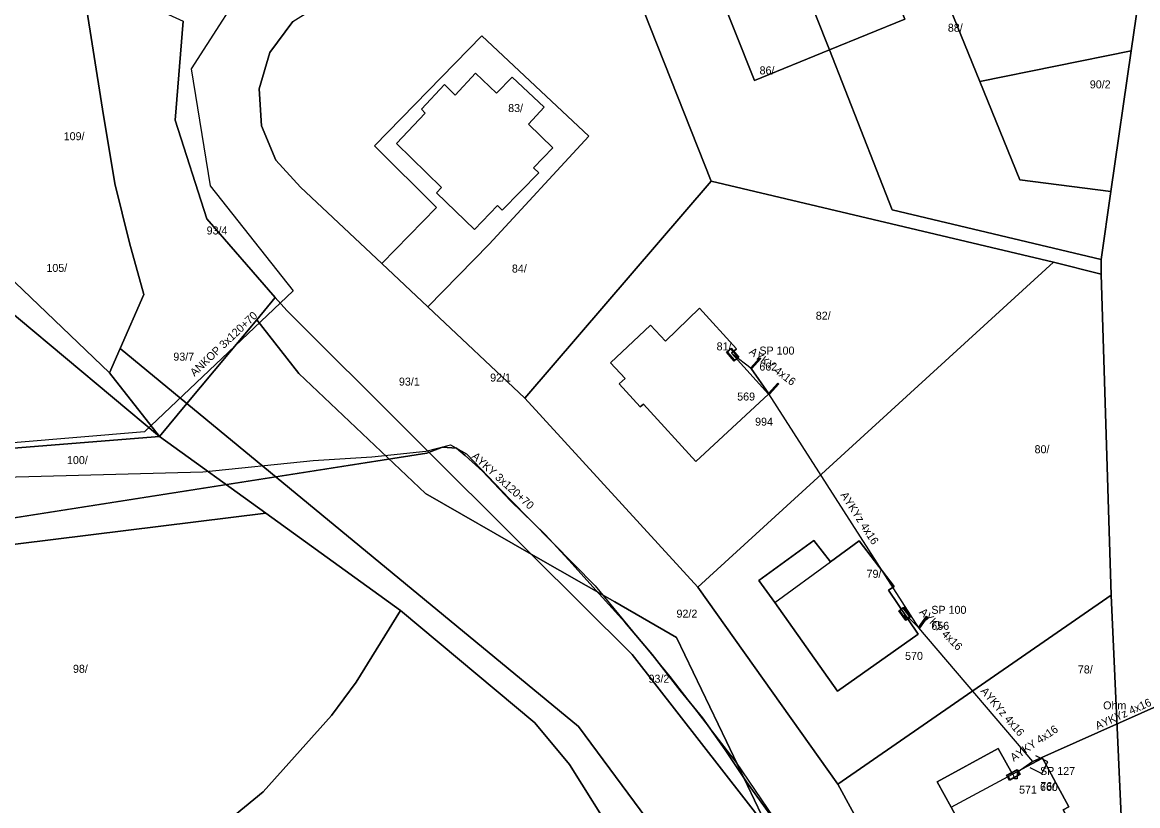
# Model space of a CAD drawing. Extents: x -793400 to -756198, y -1074141 to -1042963.
# Drawn here: x -783438.8 to -783334.3, y -1065213.5 to -1065140.1 of the extents above; entities that cross this region are included whole.
import ezdxf

# ---------------------------------------------------------------- set-up
doc = ezdxf.new("R2010")
doc.units = 0
for name, color, linetype in [('Parcela', 7, 'Continuous'), ('PB nn', 7, 'Continuous'), ('Popiskový text - Parcela', 7, 'Continuous'), ('Popiskový text - PB nn - sk_2 - SJZ', 7, 'Continuous'), ('Popiskový text - Přípojková skříň nn - SJZ', 7, 'Continuous'), ('Popiskový text - Přípojková skříň nn - Typ', 7, 'Continuous'), ('Popiskový text - Uzemnění - Odpor', 7, 'Continuous'), ('Popiskový text - Vedení nn kabelové', 7, 'Continuous'), ('Popiskový text - Vedení nn svod', 7, 'Continuous'), ('Popiskový text - Vedení nn venkovní izol', 7, 'Continuous'), ('Skříň', 7, 'Continuous'), ('Spojnice nn', 7, 'Continuous'), ('Spojnice vn', 7, 'Continuous'), ('Stavební objekt', 7, 'Continuous'), ('Vedení 22 kV kabelové', 7, 'Continuous'), ('Vedení nn kabelové', 7, 'Continuous'), ('Vedení nn svod', 7, 'Continuous'), ('Vedení nn venkovní izolované', 7, 'Continuous')]:
    doc.layers.add(name, color=color, linetype=linetype)

msp = doc.modelspace()

# ---------------------------------------------------------------- linework, layer by layer
at = {"layer": 'Parcela'}
for points in [[(-783334.89, -1065142.75), (-783349.08, -1065145.61), (-783359.09, -1065121.02), (-783336.58, -1065111.89), (-783333.19, -1065112.61), (-783331.29, -1065114.46), (-783330.21, -1065117.78), (-783332.76, -1065128.1)], [(-783333.46, -1065173.04), (-783333.27, -1065184.1), (-783332.18, -1065183.83), (-783332.44, -1065204.1), (-783331.2, -1065229.69), (-783329.02, -1065234.74), (-783333.33, -1065281.22), (-783340.36, -1065267.55), (-783335.58, -1065250.68), (-783334.84, -1065248.08), (-783334.44, -1065245.21), (-783335.73, -1065216.58), (-783336.76, -1065193.79), (-783337.72, -1065163.69), (-783337.71, -1065162.3), (-783336.8, -1065155.92), (-783334.89, -1065142.75), (-783332.76, -1065128.1), (-783330.21, -1065117.78), (-783325.71, -1065116.67), (-783328.95, -1065129.54), (-783331.93, -1065148.39), (-783333.28, -1065158.38), (-783333.36, -1065165.67)], [(-783359.09, -1065121.02), (-783349.08, -1065145.61), (-783345.34, -1065154.82), (-783336.8, -1065155.92), (-783337.71, -1065162.3), (-783357.29, -1065157.65), (-783363.17, -1065142.65), (-783356.12, -1065139.77), (-783359.98, -1065130.16), (-783367.03, -1065132.96), (-783370.11, -1065125.47)], [(-783374.09, -1065135.77), (-783370.22, -1065145.53), (-783363.17, -1065142.65), (-783357.29, -1065157.65), (-783337.71, -1065162.3), (-783337.72, -1065163.69), (-783342.17, -1065162.55), (-783374.26, -1065154.97), (-783383.74, -1065131.01), (-783370.11, -1065125.47), (-783367.03, -1065132.96)], [(-783356.12, -1065139.77), (-783363.17, -1065142.65), (-783367.03, -1065132.96), (-783359.98, -1065130.16)], [(-783383.74, -1065131.01), (-783374.26, -1065154.97), (-783391.75, -1065175.3), (-783400.84, -1065166.73), (-783395.07, -1065160.86), (-783385.75, -1065150.75), (-783395.76, -1065141.32), (-783405.84, -1065151.66), (-783400.01, -1065157.44), (-783405.15, -1065162.67), (-783412.76, -1065155.51), (-783415.07, -1065153), (-783416.41, -1065149.77), (-783416.64, -1065146.29), (-783415.63, -1065142.9), (-783413.48, -1065139.98), (-783410.44, -1065138.09)], [(-783363.17, -1065142.65), (-783370.22, -1065145.53), (-783374.09, -1065135.77), (-783367.03, -1065132.96)], [(-783416.87, -1065167.97), (-783423.43, -1065175.81), (-783429.68, -1065170.65), (-783427.46, -1065165.58), (-783428.81, -1065160.75), (-783430.17, -1065155.19), (-783431.34, -1065148.2), (-783433, -1065137.71), (-783432.01, -1065136.13), (-783425.83, -1065139.01), (-783423.77, -1065139.97), (-783424.51, -1065149.24), (-783421.56, -1065158.5), (-783415.13, -1065165.88)], [(-783433, -1065137.71), (-783431.34, -1065148.2), (-783430.17, -1065155.19), (-783428.81, -1065160.75), (-783427.46, -1065165.58), (-783429.68, -1065170.65), (-783430.68, -1065172.94), (-783446.93, -1065157.4), (-783446.89, -1065157.28), (-783447.25, -1065153.59), (-783445.62, -1065150.92), (-783447.67, -1065149.41), (-783450, -1065147.55), (-783450.24, -1065147.87), (-783451.27, -1065147.1), (-783449.11, -1065143.27), (-783443.11, -1065146.26), (-783440.09, -1065139.19)], [(-783395.07, -1065160.86), (-783400.84, -1065166.73), (-783405.15, -1065162.67), (-783400.01, -1065157.44), (-783405.84, -1065151.66), (-783395.76, -1065141.32), (-783385.75, -1065150.75)], [(-783334.89, -1065142.75), (-783336.8, -1065155.92), (-783345.34, -1065154.82), (-783349.08, -1065145.61)], [(-783342.17, -1065162.55), (-783375.51, -1065193.02), (-783391.75, -1065175.3), (-783374.26, -1065154.97)], [(-783430.68, -1065172.94), (-783426, -1065178.89), (-783448.04, -1065160.47), (-783447.05, -1065157.72), (-783446.93, -1065157.4)], [(-783452.51, -1065181.01), (-783462.8, -1065182.31), (-783462.64, -1065176.13), (-783453.07, -1065175.27), (-783453.17, -1065164.1), (-783453.76, -1065160.93), (-783453.28, -1065158.57), (-783448.04, -1065160.47), (-783426, -1065178.89), (-783449.86, -1065180.82), (-783451.98, -1065180.95)], [(-783336.76, -1065193.79), (-783362.38, -1065211.5), (-783375.51, -1065193.02), (-783342.17, -1065162.55), (-783337.72, -1065163.69)], [(-783414.06, -1065167.1), (-783391.13, -1065189.93), (-783401.04, -1065184.24), (-783412.92, -1065172.99), (-783416.87, -1065167.97), (-783415.13, -1065165.88)], [(-783375.37, -1065166.88), (-783371.9, -1065170.69), (-783372.35, -1065171.09), (-783368.88, -1065174.92), (-783375.71, -1065181.24), (-783380.62, -1065175.86), (-783380.92, -1065176.13), (-783382.9, -1065173.97), (-783382.34, -1065173.46), (-783383.7, -1065171.99), (-783379.95, -1065168.47), (-783378.54, -1065169.96)], [(-783375.37, -1065166.88), (-783378.54, -1065169.96), (-783379.95, -1065168.47), (-783383.7, -1065171.99), (-783382.34, -1065173.46), (-783382.9, -1065173.97), (-783380.92, -1065176.13), (-783380.62, -1065175.86), (-783375.71, -1065181.24), (-783368.88, -1065174.92), (-783372.35, -1065171.09), (-783371.9, -1065170.69)], [(-783346.09, -1065256.41), (-783341.85, -1065272.8), (-783351.87, -1065253.68), (-783380.31, -1065214.76), (-783386.7, -1065206.1), (-783423.43, -1065175.81), (-783416.87, -1065167.97), (-783412.92, -1065172.99), (-783401.04, -1065184.24), (-783391.13, -1065189.93), (-783381.67, -1065199.34), (-783368.9, -1065215.74)], [(-783423.43, -1065175.81), (-783426, -1065178.89), (-783430.68, -1065172.94), (-783429.68, -1065170.65)], [(-783341.85, -1065272.8), (-783345.64, -1065275.81), (-783354.48, -1065257.7), (-783360.91, -1065248.3), (-783363.87, -1065245.46), (-783374.02, -1065231.27), (-783383.09, -1065216.77), (-783387.54, -1065209.66), (-783390.81, -1065205.75), (-783403.39, -1065195.23), (-783416.03, -1065186.09), (-783426, -1065178.89), (-783423.43, -1065175.81), (-783386.7, -1065206.1), (-783380.31, -1065214.76), (-783351.87, -1065253.68)], [(-783449.1, -1065190.18), (-783453.6, -1065190.73), (-783451.98, -1065180.95), (-783449.86, -1065180.82), (-783426, -1065178.89), (-783416.03, -1065186.09)], [(-783416.03, -1065186.09), (-783403.39, -1065195.23), (-783407.54, -1065201.94), (-783409.86, -1065205.07), (-783416.28, -1065212.21), (-783421, -1065216.11), (-783424.16, -1065218.04), (-783438.03, -1065224.17), (-783441.5, -1065225.71), (-783447.41, -1065228.37), (-783452.73, -1065215.33), (-783452.34, -1065209.47), (-783459.78, -1065208.85), (-783460.26, -1065214.69), (-783460.3, -1065215.24), (-783468.73, -1065213.48), (-783469.27, -1065213.37), (-783464.68, -1065192.93), (-783464.13, -1065193.03), (-783454.3, -1065194.92), (-783453.6, -1065190.73), (-783449.1, -1065190.18)], [(-783364.63, -1065188.64), (-783363.08, -1065190.67), (-783360.38, -1065188.7), (-783357.12, -1065192.97), (-783357.65, -1065193.32), (-783354.87, -1065197.43), (-783362.42, -1065202.79), (-783368.31, -1065194.48), (-783369.79, -1065192.4)], [(-783364.63, -1065188.64), (-783369.79, -1065192.4), (-783368.31, -1065194.48), (-783362.42, -1065202.79), (-783354.87, -1065197.43), (-783357.65, -1065193.32), (-783357.12, -1065192.97), (-783360.38, -1065188.7), (-783363.08, -1065190.67)], [(-783372.84, -1065207.51), (-783368.9, -1065215.74), (-783381.67, -1065199.34), (-783391.13, -1065189.93), (-783383.31, -1065194.42), (-783377.51, -1065197.74)], [(-783336.76, -1065193.79), (-783335.73, -1065216.58), (-783338.92, -1065218.3), (-783341.26, -1065213.91), (-783340.73, -1065213.63), (-783343.2, -1065209.05), (-783346.03, -1065210.57), (-783347.35, -1065208.17), (-783353.07, -1065211.27), (-783351.78, -1065213.65), (-783346.93, -1065222.62), (-783354.11, -1065226.72), (-783362.38, -1065211.5)], [(-783383.09, -1065216.77), (-783436.26, -1065245.82), (-783436.65, -1065245.81), (-783436.74, -1065242.46), (-783438.03, -1065224.17), (-783424.16, -1065218.04), (-783421, -1065216.11), (-783416.28, -1065212.21), (-783409.86, -1065205.07), (-783407.54, -1065201.94), (-783403.39, -1065195.23), (-783390.81, -1065205.75), (-783387.54, -1065209.66)], [(-783347.35, -1065208.17), (-783346.03, -1065210.57), (-783343.2, -1065209.05), (-783340.73, -1065213.63), (-783341.26, -1065213.91), (-783338.92, -1065218.3), (-783346.93, -1065222.62), (-783351.78, -1065213.65), (-783353.07, -1065211.27)]]:
    msp.add_lwpolyline(points, close=True, dxfattribs=at)
for points in [[(-783346.09, -1065256.41), (-783368.9, -1065215.74), (-783372.84, -1065207.51), (-783377.51, -1065197.74), (-783383.31, -1065194.42), (-783391.13, -1065189.93), (-783414.06, -1065167.1), (-783415.13, -1065165.88), (-783421.56, -1065158.5), (-783424.51, -1065149.24), (-783423.77, -1065139.97)], [(-783413.48, -1065139.98), (-783415.63, -1065142.9), (-783416.64, -1065146.29), (-783416.41, -1065149.77), (-783415.07, -1065153), (-783412.76, -1065155.51), (-783405.15, -1065162.67), (-783400.84, -1065166.73), (-783391.75, -1065175.3), (-783375.51, -1065193.02), (-783362.38, -1065211.5), (-783354.11, -1065226.72), (-783342.64, -1065247.88), (-783340.83, -1065249.95), (-783338.15, -1065250.41), (-783336.55, -1065250), (-783334.84, -1065248.08), (-783335.58, -1065250.68), (-783340.36, -1065267.55)]]:
    msp.add_lwpolyline(points, dxfattribs=at)
at = {"layer": 'PB nn'}
for p, q in [((-783342.71, -1065209.41), (-783343.82, -1065208.84)), ((-783344.38, -1065209.94), (-783343.27, -1065210.51)), ((-783343.27, -1065210.51), (-783342.71, -1065209.41))]:
    msp.add_line(p, q, dxfattribs=at)
for points in [[(-783370.57, -1065172.5), (-783369.7, -1065171.52), (-783369.62, -1065171.59), (-783370.49, -1065172.56)], [(-783368.89, -1065174.86), (-783368.02, -1065173.89), (-783367.94, -1065173.95), (-783368.81, -1065174.92)], [(-783354.83, -1065196.82), (-783354.08, -1065195.76), (-783354, -1065195.81), (-783354.75, -1065196.88)]]:
    msp.add_lwpolyline(points, close=True, dxfattribs=at)
at = {"layer": 'Skříň'}
for points in [[(-783372.1, -1065171.83), (-783372.83, -1065170.98), (-783372.4, -1065170.61), (-783371.67, -1065171.46)], [(-783372.75, -1065170.98), (-783372.09, -1065171.75), (-783371.75, -1065171.46), (-783372.41, -1065170.69)], [(-783356.01, -1065196.15), (-783356.69, -1065195.25), (-783356.25, -1065194.91), (-783355.57, -1065195.81)], [(-783356.62, -1065195.26), (-783356, -1065196.07), (-783355.64, -1065195.8), (-783356.26, -1065194.99)], [(-783345.31, -1065210.61), (-783346.29, -1065211.16), (-783346.57, -1065210.67), (-783345.59, -1065210.12)], [(-783346.27, -1065211.08), (-783345.39, -1065210.59), (-783345.61, -1065210.2), (-783346.49, -1065210.69)]]:
    msp.add_lwpolyline(points, close=True, dxfattribs=at)
at = {"layer": 'Spojnice nn'}
for p, q in [((-783370.53, -1065172.53), (-783368.85, -1065174.89)), ((-783354.79, -1065196.85), (-783368.85, -1065174.89)), ((-783400.91, -1065180.45), (-783455.95, -1065189.08)), ((-783344.1, -1065209.39), (-783354.79, -1065196.85)), ((-783331.82, -1065203.88), (-783344.1, -1065209.39))]:
    msp.add_line(p, q, dxfattribs=at)
for points in [[(-783414.37, -1065132.93), (-783416.85, -1065134.84), (-783423.02, -1065144.43), (-783421.25, -1065155.41), (-783413.47, -1065165.23), (-783427.4, -1065178.48), (-783458.39, -1065181.05), (-783457.28, -1065184.72)], [(-783360.14, -1065229.05), (-783360.97, -1065227.35), (-783363.02, -1065223.74), (-783365, -1065220.66), (-783366.81, -1065217.49), (-783368.78, -1065214.31), (-783370.95, -1065211.27), (-783372.97, -1065208.27), (-783375.08, -1065205.29), (-783377.18, -1065202.72), (-783379.81, -1065199.33), (-783382.35, -1065196.31), (-783385.05, -1065193.35), (-783387.62, -1065190.49), (-783389.83, -1065188.1), (-783393.09, -1065184.92), (-783395.7, -1065182.16), (-783397.33, -1065180.69), (-783398.14, -1065180.01), (-783399.47, -1065179.91), (-783400.91, -1065180.45)]]:
    msp.add_lwpolyline(points, dxfattribs=at)
at = {"layer": 'Spojnice vn'}
msp.add_lwpolyline([(-783452.28, -1065183.03), (-783421.94, -1065182.22), (-783411.59, -1065181.15), (-783406.09, -1065180.81), (-783401.01, -1065180.27), (-783398.71, -1065179.69), (-783397.22, -1065180.54), (-783393.17, -1065184.74), (-783385.15, -1065192.91), (-783378.14, -1065201.41), (-783371.94, -1065209.46), (-783366.72, -1065217.17), (-783361.95, -1065225.31), (-783355.77, -1065235.87), (-783350.25, -1065246.43), (-783348.33, -1065249.06), (-783347.31, -1065249.68), (-783342.44, -1065250.87), (-783340.64, -1065251.31), (-783338.29, -1065251.28), (-783336.18, -1065250.61), (-783334.18, -1065248.21)], dxfattribs=at)
at = {"layer": 'Stavební objekt'}
for points in [[(-783356.12, -1065139.77), (-783363.17, -1065142.65), (-783367.03, -1065132.96), (-783359.98, -1065130.16)], [(-783363.17, -1065142.65), (-783370.22, -1065145.53), (-783374.09, -1065135.77), (-783367.03, -1065132.96)], [(-783396.35, -1065144.84), (-783394.4, -1065146.71), (-783392.91, -1065145.22), (-783389.92, -1065148.03), (-783391.38, -1065149.63), (-783389.1, -1065151.84), (-783390.91, -1065153.72), (-783390.44, -1065154.17), (-783393.86, -1065157.68), (-783394.31, -1065157.24), (-783396.47, -1065159.48), (-783400.01, -1065156.04), (-783399.54, -1065155.55), (-783403.78, -1065151.44), (-783401.08, -1065148.57), (-783401.41, -1065148.2), (-783399.26, -1065145.91), (-783398.28, -1065146.89)], [(-783375.37, -1065166.88), (-783371.9, -1065170.69), (-783372.35, -1065171.09), (-783368.88, -1065174.92), (-783375.71, -1065181.24), (-783380.62, -1065175.86), (-783380.92, -1065176.13), (-783382.9, -1065173.97), (-783382.34, -1065173.46), (-783383.7, -1065171.99), (-783379.95, -1065168.47), (-783378.54, -1065169.96)], [(-783354.87, -1065197.43), (-783362.42, -1065202.79), (-783368.31, -1065194.48), (-783363.08, -1065190.67), (-783360.38, -1065188.7), (-783357.12, -1065192.97), (-783357.65, -1065193.32)], [(-783338.92, -1065218.3), (-783346.93, -1065222.62), (-783351.78, -1065213.65), (-783346.03, -1065210.57), (-783343.2, -1065209.05), (-783340.73, -1065213.63), (-783341.26, -1065213.91)]]:
    msp.add_lwpolyline(points, close=True, dxfattribs=at)
at = {"layer": 'Vedení 22 kV kabelové'}
msp.add_lwpolyline([(-783452.28, -1065183.03), (-783421.94, -1065182.22), (-783411.59, -1065181.15), (-783406.09, -1065180.81), (-783401.01, -1065180.27), (-783398.71, -1065179.69), (-783397.22, -1065180.54), (-783393.17, -1065184.74), (-783385.15, -1065192.91), (-783378.14, -1065201.41), (-783371.94, -1065209.46), (-783366.72, -1065217.17), (-783361.95, -1065225.31), (-783355.77, -1065235.87), (-783350.25, -1065246.43), (-783348.33, -1065249.06), (-783347.31, -1065249.68), (-783342.44, -1065250.87), (-783340.64, -1065251.31), (-783338.29, -1065251.28), (-783336.18, -1065250.61), (-783334.18, -1065248.21)], dxfattribs=at)
at = {"layer": 'Vedení nn kabelové'}
for points in [[(-783414.76, -1065132.34), (-783414.76, -1065132.35), (-783414.76, -1065132.74), (-783414.53, -1065133.05), (-783416.85, -1065134.84), (-783423.02, -1065144.43), (-783421.25, -1065155.41), (-783413.47, -1065165.23), (-783427.4, -1065178.48), (-783458.39, -1065181.05), (-783456.25, -1065187.99), (-783454.71, -1065187.99), (-783454.71, -1065190.35), (-783455.75, -1065190.35), (-783455.75, -1065189.56)], [(-783455.41, -1065188.99), (-783400.91, -1065180.45), (-783399.47, -1065179.91), (-783398.14, -1065180.01), (-783397.33, -1065180.69), (-783395.7, -1065182.16), (-783393.09, -1065184.92), (-783389.83, -1065188.1), (-783387.62, -1065190.49), (-783385.05, -1065193.35), (-783382.35, -1065196.31), (-783379.81, -1065199.33), (-783377.18, -1065202.72), (-783375.08, -1065205.29), (-783372.97, -1065208.27), (-783370.95, -1065211.27), (-783368.78, -1065214.31), (-783366.81, -1065217.49), (-783365, -1065220.66), (-783363.02, -1065223.74), (-783360.97, -1065227.35), (-783360.14, -1065229.05)]]:
    msp.add_lwpolyline(points, dxfattribs=at)
at = {"layer": 'Vedení nn svod'}
msp.add_line((-783370.53, -1065172.53), (-783372.25, -1065171.22), dxfattribs=at)
for points in [[(-783354.79, -1065196.85), (-783355.78, -1065195.88), (-783355.78, -1065195.89), (-783356.03, -1065195.89), (-783356.13, -1065195.53)], [(-783344.1, -1065209.39), (-783345.58, -1065210.4), (-783345.58, -1065211), (-783345.84, -1065211), (-783345.94, -1065210.64)]]:
    msp.add_lwpolyline(points, dxfattribs=at)
at = {"layer": 'Vedení nn venkovní izolované'}
for q in [(-783354.79, -1065196.85), (-783331.82, -1065203.88)]:
    msp.add_line((-783344.1, -1065209.39), q, dxfattribs=at)
msp.add_lwpolyline([(-783354.79, -1065196.85), (-783368.85, -1065174.89), (-783370.53, -1065172.53)], dxfattribs=at)

# ---------------------------------------------------------------- texts
at = {"layer": 'Popiskový text - Parcela'}
for s, p in [('88/', (-783352.08, -1065140.95)), ('86/', (-783369.73, -1065144.95)), ('90/2', (-783338.77, -1065146.26)), ('83/', (-783393.3, -1065148.48)), ('109/', (-783434.97, -1065151.12)), ('93/4', (-783421.57, -1065159.96)), ('105/', (-783436.59, -1065163.47)), ('84/', (-783392.95, -1065163.53)), ('82/', (-783364.46, -1065167.95)), ('81/', (-783373.76, -1065170.83)), ('93/7', (-783424.69, -1065171.79)), ('93/1', (-783403.54, -1065174.13)), ('92/1', (-783394.99, -1065173.75)), ('80/', (-783343.95, -1065180.47)), ('100/', (-783434.66, -1065181.49)), ('79/', (-783359.7, -1065192.15)), ('92/2', (-783377.52, -1065195.89)), ('98/', (-783434.1, -1065201.06)), ('78/', (-783339.89, -1065201.12)), ('93/2', (-783380.14, -1065201.99)), ('76/', (-783343.41, -1065212.06))]:
    msp.add_text(s, height=0.75, dxfattribs=at).set_placement(p)
at = {"layer": 'Popiskový text - PB nn - sk_2 - SJZ'}
for s, p in [('569', (-783371.83, -1065175.53)), ('994', (-783370.15, -1065177.89)), ('570', (-783356.09, -1065199.85)), ('571', (-783345.4, -1065212.39))]:
    msp.add_text(s, height=0.75, dxfattribs=at).set_placement(p)
at = {"layer": 'Popiskový text - Přípojková skříň nn - SJZ'}
for s, p in [('662', (-783369.75, -1065172.72)), ('656', (-783353.63, -1065197.03)), ('660', (-783343.44, -1065212.14))]:
    msp.add_text(s, height=0.75, dxfattribs=at).set_placement(p)
at = {"layer": 'Popiskový text - Přípojková skříň nn - Typ'}
for s, p in [('SP 100', (-783369.75, -1065171.22)), ('SP 100', (-783353.63, -1065195.53)), ('SP 127', (-783343.44, -1065210.64))]:
    msp.add_text(s, height=0.75, dxfattribs=at).set_placement(p)
at = {"layer": 'Popiskový text - Uzemnění - Odpor'}
msp.add_text(' Ohm', height=0.75, dxfattribs=at).set_placement((-783337.8, -1065204.49))
at = {"layer": 'Popiskový text - Vedení nn kabelové'}
for s, rotation, p in [('ANKOP 3x120+70', 43.5448, (-783422.7, -1065173.32)), ('AYKY 3x120+70', 317.9343, (-783396.78, -1065180.85))]:
    msp.add_text(s, height=0.75, rotation=rotation, dxfattribs=at).set_placement(p)
at = {"layer": 'Popiskový text - Vedení nn svod'}
for rotation, p in [(322.6898, (-783370.78, -1065171.08)), (315.4133, (-783354.81, -1065195.43)), (34.2056, (-783345.91, -1065209.41))]:
    msp.add_text('AYKY 4x16', height=0.75, rotation=rotation, dxfattribs=at).set_placement(p)
at = {"layer": 'Popiskový text - Vedení nn venkovní izol'}
for rotation, p in [(302.6363, (-783362.18, -1065184.38)), (310.4285, (-783349.06, -1065202.8)), (24.1788, (-783338.06, -1065206.41))]:
    msp.add_text('AYKYz 4x16', height=0.75, rotation=rotation, dxfattribs=at).set_placement(p)

doc.saveas('drawing.dxf')
